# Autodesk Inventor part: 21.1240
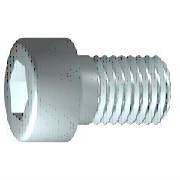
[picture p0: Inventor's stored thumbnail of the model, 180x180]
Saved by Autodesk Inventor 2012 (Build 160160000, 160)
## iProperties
Created: 2006-02
Part Number: 21.1240
Material: Steel, Mild
Description: M6x20 SHCS
Document SubType Name: Modeling
Standard: DIN 7984
Designer: Andy Moles
Standards Organization: DIN
Language: en-US
Size Designation: M6 x 20
Categories: <MemberInstance><Categories><Category DisplayName="Fasteners" InternalName="e4da775c-781d-43d5-af7c-5136215cf5a6" Mnemonic="FSTN"><Category DisplayName="Bolts"
Density: 7.86 g/cm^3
Vendor: S
Mass: 6.48581 g
Surface Area: 6.89561 cm^2
Volume: 0.825167 cm^3
Author: Andy Moles
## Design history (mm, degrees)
workplane "Work Plane1"
revolve "Body" stored, may be unused: angle "d10" = 90 deg
sketch "Sketch2"
  geometry: L1 (0, -7)-(0, 7) reference; L2 (-7, 0)-(7, 0) reference; L3 (2.309, 0)-(1.155, -2); L4 (1.155, -2)-(-1.155, -2); L5 (-1.155, -2)-(-2.309, 0); L6 (-2.309, 0)-(-1.155, 2); L7 (-1.155, 2)-(1.155, 2); L8 (1.155, 2)-(2.309, 0); 2 further points
  constraints: 12 end point, 1 coincident, 1 horizontal alignment, 1 point on line, 12 other
extrude "Slot" join sketch "Sketch2" stored distance "d11" = 10; taper "d12" = 0 deg
body "Solid1"
fillet "Fillet1" dims "d17" = 0.6 (= RR)
feature "Thread" dims "d13" = 20, "d14" = 0
chamfer "Chamfer1" distance "d15" = 0.61345 (= -0.5 x SPD + 0.5 x GD); stored, may be unused: second distance "d16" = 0.61345 (= GUL), angle "d27" = 45 deg
sketch "Sketch1"
  geometry: L1 (0.333, 0)-(20, 0); L2 (20, 0)-(20, 3); L3 (20, 3)-(3, 3); L4 (3, 3)-(2.386, 3); L5 (2.386, 3)-(0, 3); L6 (0, 3)-(0, 5); L7 (0, 5)-(-4, 5); L8 (-4, 5)-(-4, 2.309); L9 (-4, 2.309)-(-1, 2.309); L10 (-1, 2.309)-(0.333, 0); L11 (-8.8, 0)-(24.8, 0) reference; L12 (0, -1)-(0, 6) reference; L13 (3, 3)-(0, 3)
  constraints: 22 end point, 6 parallel, 2 collinear, 2 perpendicular, 1 horizontal, 1 point on line
  dimensions: "d1" = 17 distance from line of L3.end L2 (= GEL); "d2" = 0.61355 distance of L4.end L3.end (computed from GAL); "d3" = 4 distance between parallel lines of L8 L6 (= KOH); "d4" = 3 distance of L8.end L9.end (= INTI); "d5" = 60 deg angle of L10 L1; "d6" = 6 diameter of L3 L1 (= GD); "d7" = 6 diameter of L5 L1 (= BDM); "d8" = 4.6188 diameter of L9 L1 (= 1.1547 x SW); "d9" = 10 diameter of L7 L1 (= KOD); "d26" = 20 distance between parallel lines of L12 L2 (= NLG)
other parameters: "GD" = 6 (= NND) [user parameter; used in 2 equation terms], "NLG" = 20 [user parameter; used in 1 equation term], "GEL" = 17 [user parameter; used in 1 equation term], "KOD" = 10 [user parameter; used in 1 equation term], "KOH" = 4 [user parameter; used in 1 equation term], "INTI" = 3 [user parameter; used in 1 equation term], "GAL" = 0.61345 (= 0.61345 x PTC) [user parameter; used in 1 equation term], "GUL" = 0.61345 (= 0.61345 x PTC) [user parameter; used in 1 equation term], "BDM" = 6 (= NND) [user parameter; used in 1 equation term], "SW" = 4 [user parameter; used in 2 equation terms], "RR" = 0.6 [user parameter; used in 1 equation term], "SPD" = 4.7731 (= NND - 1.2269 x PTC) [user parameter; used in 1 equation term], "d19" = 0, "d28" = 0, "d29" = 0, "TOA" = 30 deg [user parameter], "GD1" = 4.7731 (= THREADDIA - 1.2269 x PTC) [user parameter], "THREADDIA" = 6 [user parameter; used in 1 equation term], "FAWI" = 45 deg [user parameter], "ANG" = 120 deg [user parameter], "PTC" = 1 [user parameter; used in 5 equation terms], "NND" = 6 [user parameter; used in 3 equation terms], "E0" = 4.62 (= 1.155 x SW) [user parameter]
